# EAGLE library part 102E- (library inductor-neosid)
FILTER dual helix bandpass filter, type E
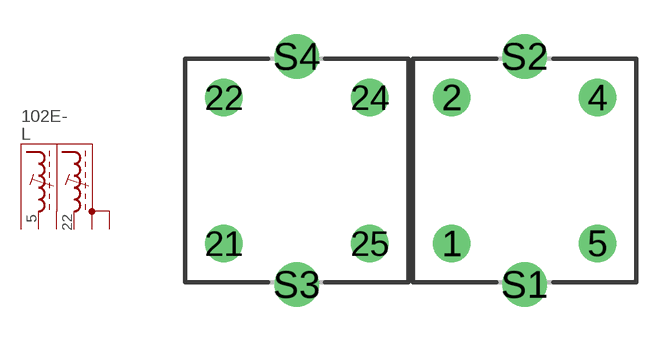
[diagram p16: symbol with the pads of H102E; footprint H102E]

Designator prefix L

## 102E-5-22 (OC_FARNELL: unknown; OC_NEWARK: unknown)  [H102E]
5  IN  pas
22  OUT  pas
S1  S1  pas
S2  S2  pas
S3  S3  pas
S4  S4  pas

## 102E-4-24 (OC_FARNELL: unknown; OC_NEWARK: unknown)  [H102E]
4  IN  pas
22  OUT  pas
S1  S1  pas
S2  S2  pas
S3  S3  pas
S4  S4  pas

## 102E-4-21 (OC_FARNELL: unknown; OC_NEWARK: unknown)  [H102E]
4  IN  pas
21  OUT  pas
S1  S1  pas
S2  S2  pas
S3  S3  pas
S4  S4  pas

## Footprint H102E (pad centres in mm)
DUAL RF COIL ASSEMBLY 10.1, 4 pads, grid 2.5, 10 x 10 x 15 mm
drill 1.1 round: 1 1.8,-3.2; 2 1.8,3.2; 4 8.2,3.2; 5 8.2,-3.2; 21 -8.2,-3.2; 22 -8.2,3.2; 24 -1.8,3.2; 25 -1.8,-3.2
drill 1.3 round: S1 5,-5; S2 5,5; S3 -5,-5; S4 -5,5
